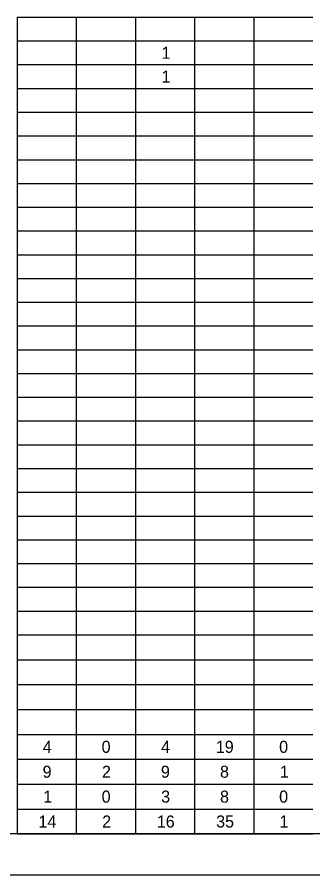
# Model space of a CAD drawing. Extents: x 0 to 34, y 0 to 22.
# Drawn here: x 23.33 to 26.95, y 0 to 10.47 of the extents above; entities that cross this region are included whole.
import ezdxf

# ---------------------------------------------------------------- set-up
doc = ezdxf.new("R2010")
doc.units = 0
for name, color, linetype in [('Default', 7, 'Continuous'), ('SH_Border', 7, 'Continuous'), ('SH_Cut_Line', 7, 'Continuous')]:
    doc.layers.add(name, color=color, linetype=linetype)

msp = doc.modelspace()

# ---------------------------------------------------------------- linework, layer by layer
at = {"layer": 'Default'}
for p, q in [((23.33, 10.475), (24.054, 10.475)), ((23.33, 10.475), (23.33, 10.185)), ((24.054, 10.475), (26.224, 10.475)), ((24.054, 10.475), (24.054, 10.185)), ((24.777, 10.475), (24.777, 10.185)), ((25.501, 10.475), (25.501, 10.185)), ((26.224, 10.475), (26.948, 10.475)), ((26.224, 10.475), (26.224, 10.185)), ((23.33, 10.185), (24.054, 10.185)), ((23.33, 10.185), (23.33, 9.895)), ((24.054, 10.185), (26.224, 10.185)), ((24.054, 10.185), (24.054, 9.895)), ((24.777, 10.185), (24.777, 9.895)), ((25.501, 10.185), (25.501, 9.895)), ((26.224, 10.185), (26.948, 10.185)), ((26.224, 10.185), (26.224, 9.895)), ((23.33, 9.895), (24.054, 9.895)), ((23.33, 9.895), (23.33, 9.604)), ((24.054, 9.895), (26.224, 9.895)), ((24.054, 9.895), (24.054, 9.604)), ((24.777, 9.895), (24.777, 9.604)), ((25.501, 9.895), (25.501, 9.604)), ((26.224, 9.895), (26.948, 9.895)), ((26.224, 9.895), (26.224, 9.604)), ((23.33, 9.604), (24.054, 9.604)), ((23.33, 9.604), (23.33, 9.314)), ((24.054, 9.604), (26.224, 9.604)), ((24.054, 9.604), (24.054, 9.314)), ((24.777, 9.604), (24.777, 9.314)), ((25.501, 9.604), (25.501, 9.314)), ((26.224, 9.604), (26.948, 9.604)), ((26.224, 9.604), (26.224, 9.314)), ((23.33, 9.314), (24.054, 9.314)), ((23.33, 9.314), (23.33, 9.024)), ((24.054, 9.314), (26.224, 9.314)), ((24.054, 9.314), (24.054, 9.024)), ((24.777, 9.314), (24.777, 9.024)), ((25.501, 9.314), (25.501, 9.024)), ((26.224, 9.314), (26.948, 9.314)), ((26.224, 9.314), (26.224, 9.024)), ((23.33, 9.024), (24.054, 9.024)), ((23.33, 9.024), (23.33, 8.734)), ((24.054, 9.024), (26.224, 9.024)), ((24.054, 9.024), (24.054, 8.734)), ((24.777, 9.024), (24.777, 8.734)), ((25.501, 9.024), (25.501, 8.734)), ((26.224, 9.024), (26.948, 9.024)), ((26.224, 9.024), (26.224, 8.734)), ((23.33, 8.734), (24.054, 8.734)), ((23.33, 8.734), (23.33, 8.444)), ((24.054, 8.734), (26.224, 8.734)), ((24.054, 8.734), (24.054, 8.444)), ((24.777, 8.734), (24.777, 8.444)), ((25.501, 8.734), (25.501, 8.444)), ((26.224, 8.734), (26.948, 8.734)), ((26.224, 8.734), (26.224, 8.444)), ((23.33, 8.444), (24.054, 8.444)), ((23.33, 8.444), (23.33, 8.154)), ((24.054, 8.444), (26.224, 8.444)), ((24.054, 8.444), (24.054, 8.154)), ((24.777, 8.444), (24.777, 8.154)), ((25.501, 8.444), (25.501, 8.154)), ((26.224, 8.444), (26.948, 8.444)), ((26.224, 8.444), (26.224, 8.154)), ((23.33, 8.154), (24.054, 8.154)), ((23.33, 8.154), (23.33, 7.864)), ((24.054, 8.154), (26.224, 8.154)), ((24.054, 8.154), (24.054, 7.864)), ((24.777, 8.154), (24.777, 7.864)), ((25.501, 8.154), (25.501, 7.864)), ((26.224, 8.154), (26.948, 8.154)), ((26.224, 8.154), (26.224, 7.864)), ((23.33, 7.864), (24.054, 7.864)), ((23.33, 7.864), (23.33, 7.574)), ((24.054, 7.864), (26.224, 7.864)), ((24.054, 7.864), (24.054, 7.574)), ((24.777, 7.864), (24.777, 7.574)), ((25.501, 7.864), (25.501, 7.574)), ((26.224, 7.864), (26.948, 7.864)), ((26.224, 7.864), (26.224, 7.574)), ((23.33, 7.574), (24.054, 7.574)), ((23.33, 7.574), (23.33, 7.283)), ((24.054, 7.574), (26.224, 7.574)), ((24.054, 7.574), (24.054, 7.283)), ((24.777, 7.574), (24.777, 7.283)), ((25.501, 7.574), (25.501, 7.283)), ((26.224, 7.574), (26.948, 7.574)), ((26.224, 7.574), (26.224, 7.283)), ((23.33, 7.283), (24.054, 7.283)), ((23.33, 7.283), (23.33, 6.993)), ((24.054, 7.283), (26.224, 7.283)), ((24.054, 7.283), (24.054, 6.993)), ((24.777, 7.283), (24.777, 6.993)), ((25.501, 7.283), (25.501, 6.993)), ((26.224, 7.283), (26.948, 7.283)), ((26.224, 7.283), (26.224, 6.993)), ((23.33, 6.993), (24.054, 6.993)), ((23.33, 6.993), (23.33, 6.703)), ((24.054, 6.993), (26.224, 6.993)), ((24.054, 6.993), (24.054, 6.703)), ((24.777, 6.993), (24.777, 6.703)), ((25.501, 6.993), (25.501, 6.703)), ((26.224, 6.993), (26.948, 6.993)), ((26.224, 6.993), (26.224, 6.703)), ((23.33, 6.703), (24.054, 6.703)), ((23.33, 6.703), (23.33, 6.413)), ((24.054, 6.703), (26.224, 6.703)), ((24.054, 6.703), (24.054, 6.413)), ((24.777, 6.703), (24.777, 6.413)), ((25.501, 6.703), (25.501, 6.413)), ((26.224, 6.703), (26.948, 6.703)), ((26.224, 6.703), (26.224, 6.413)), ((23.33, 6.413), (24.054, 6.413)), ((23.33, 6.413), (23.33, 6.123)), ((24.054, 6.413), (26.224, 6.413)), ((24.054, 6.413), (24.054, 6.123)), ((24.777, 6.413), (24.777, 6.123)), ((25.501, 6.413), (25.501, 6.123)), ((26.224, 6.413), (26.948, 6.413)), ((26.224, 6.413), (26.224, 6.123)), ((23.33, 6.123), (24.054, 6.123)), ((23.33, 6.123), (23.33, 5.833)), ((24.054, 6.123), (26.224, 6.123)), ((24.054, 6.123), (24.054, 5.833)), ((24.777, 6.123), (24.777, 5.833)), ((25.501, 6.123), (25.501, 5.833)), ((26.224, 6.123), (26.948, 6.123)), ((26.224, 6.123), (26.224, 5.833)), ((23.33, 5.833), (24.054, 5.833)), ((23.33, 5.833), (23.33, 5.543)), ((24.054, 5.833), (26.224, 5.833)), ((24.054, 5.833), (24.054, 5.543)), ((24.777, 5.833), (24.777, 5.543)), ((25.501, 5.833), (25.501, 5.543)), ((26.224, 5.833), (26.948, 5.833)), ((26.224, 5.833), (26.224, 5.543)), ((23.33, 5.543), (24.054, 5.543)), ((23.33, 5.543), (23.33, 5.252)), ((24.054, 5.543), (26.224, 5.543)), ((24.054, 5.543), (24.054, 5.252)), ((24.777, 5.543), (24.777, 5.252)), ((25.501, 5.543), (25.501, 5.252)), ((26.224, 5.543), (26.948, 5.543)), ((26.224, 5.543), (26.224, 5.252)), ((23.33, 5.252), (24.054, 5.252)), ((23.33, 5.252), (23.33, 4.672)), ((24.054, 5.252), (26.224, 5.252)), ((24.054, 5.252), (24.054, 4.672)), ((24.777, 5.252), (24.777, 4.672)), ((25.501, 5.252), (25.501, 4.672)), ((26.224, 5.252), (26.948, 5.252)), ((26.224, 5.252), (26.224, 4.672)), ((23.33, 4.962), (24.054, 4.962)), ((24.054, 4.962), (26.224, 4.962)), ((26.224, 4.962), (26.948, 4.962)), ((23.33, 4.672), (24.054, 4.672)), ((23.33, 4.672), (23.33, 4.092)), ((24.054, 4.672), (26.224, 4.672)), ((24.054, 4.672), (24.054, 4.092)), ((24.777, 4.672), (24.777, 4.092)), ((25.501, 4.672), (25.501, 4.092)), ((26.224, 4.672), (26.948, 4.672)), ((26.224, 4.672), (26.224, 4.092)), ((23.33, 4.382), (24.054, 4.382)), ((24.054, 4.382), (26.224, 4.382)), ((26.224, 4.382), (26.948, 4.382)), ((23.33, 4.092), (24.054, 4.092)), ((23.33, 4.092), (23.33, 3.802)), ((24.054, 4.092), (26.224, 4.092)), ((24.054, 4.092), (24.054, 3.802)), ((24.777, 4.092), (24.777, 3.802)), ((25.501, 4.092), (25.501, 3.802)), ((26.224, 4.092), (26.948, 4.092)), ((26.224, 4.092), (26.224, 3.802)), ((23.33, 3.802), (24.054, 3.802)), ((23.33, 3.802), (23.33, 3.222)), ((24.054, 3.802), (26.224, 3.802)), ((24.054, 3.802), (24.054, 3.222)), ((24.777, 3.802), (24.777, 3.222)), ((25.501, 3.802), (25.501, 3.222)), ((26.224, 3.802), (26.948, 3.802)), ((26.224, 3.802), (26.224, 3.222)), ((23.33, 3.512), (24.054, 3.512)), ((24.054, 3.512), (26.224, 3.512)), ((26.224, 3.512), (26.948, 3.512)), ((23.33, 3.222), (24.054, 3.222)), ((23.33, 3.222), (23.33, 2.627)), ((24.054, 3.222), (26.224, 3.222)), ((24.054, 3.222), (24.054, 2.627)), ((24.777, 3.222), (24.777, 2.627)), ((25.501, 3.222), (25.501, 2.627)), ((26.224, 3.222), (26.948, 3.222)), ((26.224, 3.222), (26.224, 2.627)), ((23.33, 2.931), (24.054, 2.931)), ((24.054, 2.931), (26.224, 2.931)), ((26.224, 2.931), (26.948, 2.931)), ((23.33, 2.627), (24.054, 2.627)), ((23.33, 2.627), (23.33, 2.323)), ((24.054, 2.627), (26.224, 2.627)), ((24.054, 2.627), (24.054, 2.323)), ((24.777, 2.627), (24.777, 2.323)), ((25.501, 2.627), (25.501, 2.323)), ((26.224, 2.627), (26.948, 2.627)), ((26.224, 2.627), (26.224, 2.323)), ((23.33, 2.323), (24.054, 2.323)), ((23.33, 2.323), (23.33, 2.02)), ((24.054, 2.323), (26.224, 2.323)), ((24.054, 2.323), (24.054, 2.02)), ((24.777, 2.323), (24.777, 2.02)), ((25.501, 2.323), (25.501, 2.02)), ((26.224, 2.323), (26.948, 2.323)), ((26.224, 2.323), (26.224, 2.02)), ((23.33, 2.02), (24.054, 2.02)), ((23.33, 2.02), (23.33, 1.716)), ((24.054, 2.02), (26.224, 2.02)), ((24.054, 2.02), (24.054, 1.716)), ((24.777, 2.02), (24.777, 1.716)), ((25.501, 2.02), (25.501, 1.716)), ((26.224, 2.02), (26.948, 2.02)), ((26.224, 2.02), (26.224, 1.716)), ((23.33, 1.716), (24.054, 1.716)), ((23.33, 1.716), (23.33, 1.412)), ((24.054, 1.716), (26.224, 1.716)), ((24.054, 1.716), (24.054, 1.412)), ((24.777, 1.716), (24.777, 1.412)), ((25.501, 1.716), (25.501, 1.412)), ((26.224, 1.716), (26.948, 1.716)), ((26.224, 1.716), (26.224, 1.412)), ((23.33, 1.412), (24.054, 1.412)), ((23.33, 1.412), (23.33, 1.108)), ((24.054, 1.412), (26.224, 1.412)), ((24.054, 1.412), (24.054, 1.108)), ((24.777, 1.412), (24.777, 1.108)), ((25.501, 1.412), (25.501, 1.108)), ((26.224, 1.412), (26.948, 1.412)), ((26.224, 1.412), (26.224, 1.108)), ((23.33, 1.108), (24.054, 1.108)), ((23.33, 1.108), (23.33, 0.804)), ((24.054, 1.108), (26.224, 1.108)), ((24.054, 1.108), (24.054, 0.804)), ((24.777, 1.108), (24.777, 0.804)), ((25.501, 1.108), (25.501, 0.804)), ((26.224, 1.108), (26.948, 1.108)), ((26.224, 1.108), (26.224, 0.804)), ((23.33, 0.804), (24.054, 0.804)), ((23.33, 0.804), (23.33, 0.5)), ((24.054, 0.804), (26.224, 0.804)), ((24.054, 0.804), (24.054, 0.5)), ((24.777, 0.804), (24.777, 0.5)), ((25.501, 0.804), (25.501, 0.5)), ((26.224, 0.804), (26.948, 0.804)), ((26.224, 0.804), (26.224, 0.5)), ((23.33, 0.5), (24.054, 0.5)), ((24.054, 0.5), (26.224, 0.5)), ((26.224, 0.5), (26.948, 0.5))]:
    msp.add_line(p, q, dxfattribs=at)
at = {"layer": 'SH_Border'}
msp.add_lwpolyline([(1.5, 21.5), (33.5, 21.5), (33.5, 0.5), (1.5, 0.5)], close=True, dxfattribs=at)
at = {"layer": 'SH_Cut_Line'}
msp.add_lwpolyline([(0, 0), (34, 0), (34, 22), (0, 22)], close=True, dxfattribs=at)

# ---------------------------------------------------------------- texts
at = {"layer": 'Default'}
for s, height, p in [('1', 0.147, (25.097, 9.966)), ('1', 0.147, (25.097, 9.676)), ('4', 0.147, (23.644, 1.49)), ('0', 0.147, (24.364, 1.49)), ('4', 0.147, (25.091, 1.49)), ('19', 0.1468, (25.761, 1.49)), ('0', 0.147, (26.535, 1.49)), ('9', 0.147, (23.642, 1.186)), ('2', 0.147, (24.368, 1.186)), ('9', 0.147, (25.089, 1.186)), ('8', 0.147, (25.812, 1.186)), ('1', 0.147, (26.544, 1.186)), ('1', 0.147, (23.65, 0.882)), ('0', 0.147, (24.364, 0.882)), ('3', 0.147, (25.092, 0.882)), ('8', 0.147, (25.812, 0.882)), ('0', 0.147, (26.535, 0.882)), ('14', 0.1468, (23.591, 0.578)), ('2', 0.147, (24.37, 0.578)), ('16', 0.1468, (25.039, 0.578)), ('35', 0.1468, (25.765, 0.578)), ('1', 0.147, (26.54, 0.578))]:
    msp.add_text(s, height=height, dxfattribs=at).set_placement(p)

doc.saveas('drawing.dxf')
